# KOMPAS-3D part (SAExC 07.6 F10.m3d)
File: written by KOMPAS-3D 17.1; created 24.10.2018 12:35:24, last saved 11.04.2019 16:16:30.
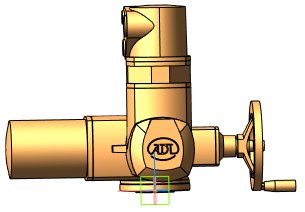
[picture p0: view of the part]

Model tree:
1. Операция без истории:2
